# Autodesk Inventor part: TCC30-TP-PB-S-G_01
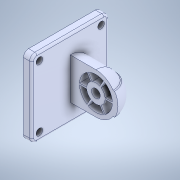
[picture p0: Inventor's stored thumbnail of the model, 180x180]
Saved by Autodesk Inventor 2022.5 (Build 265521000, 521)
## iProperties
Created: 2023-09
Part Number: TCC30-TP-PB-S-G_01
Material: 一般
Document SubType Name: Modeling
Designer: ImaoCorp
Density: 1 g/cm^3
Appearance: 既定
Author: ImaoCorp
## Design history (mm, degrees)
feature "TCC30-TP-PB-S-G_01"
node "ソリッド1"
